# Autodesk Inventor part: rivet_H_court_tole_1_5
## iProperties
Created: 2011-01
Part Number: rivet_H_court_tole_1_5
Document SubType Name: Modeling
Designer: eric
Density: 1 g/cm^3
Mass: 0.0802207 g
Surface Area: 1.85352 cm^2
Volume: 0.0802207 cm^3
Author: eric
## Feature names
1. Base1
